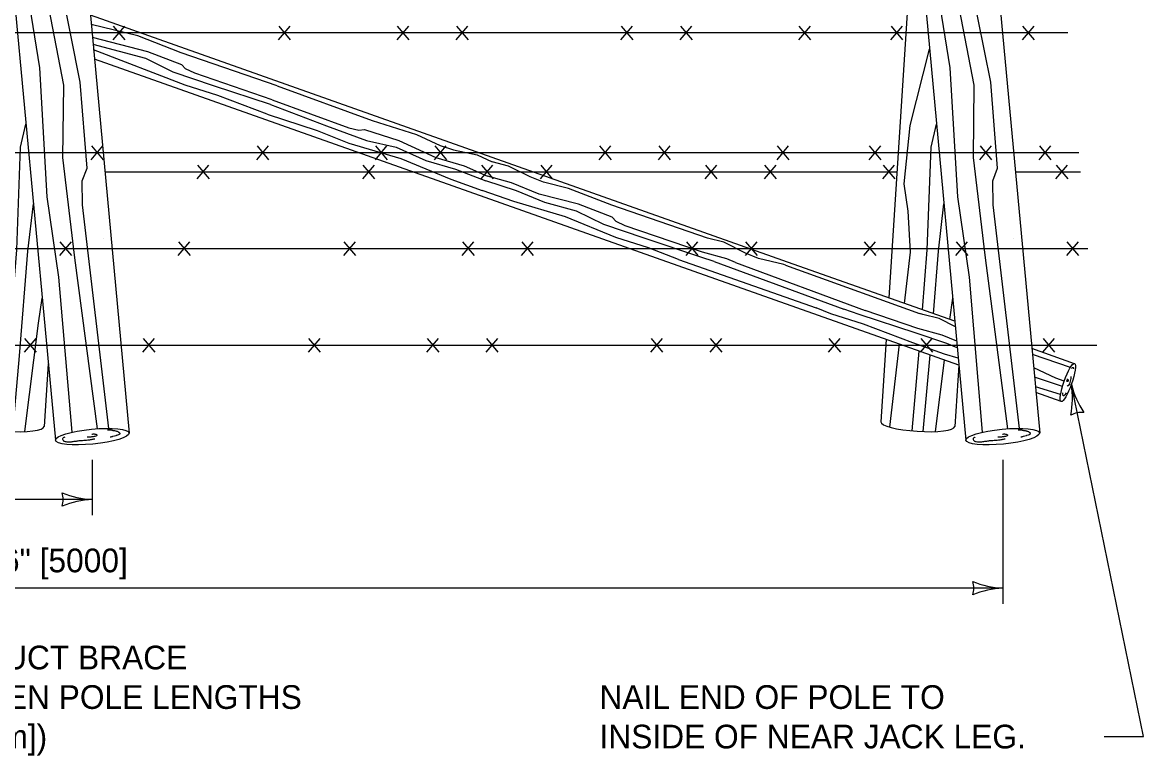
# Model space of a CAD drawing. Extents: x 49991.4 to 50021, y 49987.6 to 50011.4.
# Drawn here: x 50012.065 to 50014.903, y 49990.172 to 49992.027 of the extents above; entities that cross this region are included whole.
import ezdxf

# ---------------------------------------------------------------- set-up
doc = ezdxf.new("R2010")
doc.units = 0
for name, color, linetype in [('Level 1', 7, 'Continuous'), ('Level 2', 7, 'Continuous'), ('Level 3', 7, 'Continuous')]:
    doc.layers.add(name, color=color, linetype=linetype)

msp = doc.modelspace()

# ---------------------------------------------------------------- linework, layer by layer
at = {"layer": 'Level 1'}
for p, q in [((50014.3503, 49992.766), (50014.2579, 49991.3299)), ((50012.2063, 49992.3783), (50012.3358, 49990.9877)), ((50014.5108, 49992.3783), (50014.6403, 49990.9877)), ((50012.0223, 49992.3281), (50012.1488, 49990.9698)), ((50014.3268, 49992.3281), (50014.4534, 49990.9698)), ((50014.0306, 49991.4104), (50012.2373, 49992.0454)), ((50010.3579, 49992.001), (50012.6067, 49992.001)), ((50012.2948, 49991.9829), (50012.3242, 49992.0176)), ((50012.3255, 49991.9829), (50012.2962, 49992.0176)), ((50012.6067, 49992.001), (50014.7109, 49992.001)), ((50012.7136, 49991.9829), (50012.743, 49992.0176)), ((50012.7443, 49991.9829), (50012.715, 49992.0176)), ((50013.0136, 49991.9829), (50013.043, 49992.0176)), ((50013.0443, 49991.9829), (50013.015, 49992.0176)), ((50013.1636, 49991.9829), (50013.193, 49992.0176)), ((50013.1943, 49991.9829), (50013.165, 49992.0176)), ((50013.5803, 49991.9829), (50013.6096, 49992.0176)), ((50013.611, 49991.9829), (50013.5816, 49992.0176)), ((50013.7303, 49991.9829), (50013.7596, 49992.0176)), ((50013.761, 49991.9829), (50013.7316, 49992.0176)), ((50014.0303, 49991.9829), (50014.0596, 49992.0176)), ((50014.061, 49991.9829), (50014.0316, 49992.0176)), ((50014.2632, 49991.9829), (50014.2926, 49992.0176)), ((50014.2939, 49991.9829), (50014.2646, 49992.0176)), ((50014.5963, 49991.9829), (50014.6257, 49992.0176)), ((50014.627, 49991.9829), (50014.5977, 49992.0176)), ((50013.6705, 49991.4303), (50012.2476, 49991.9341)), ((50012.325, 49991.9265), (50012.325, 49991.9265)), ((50012.2398, 49991.6795), (50012.2692, 49991.7142)), ((50012.2705, 49991.6795), (50012.2412, 49991.7142)), ((50012.6586, 49991.6795), (50012.688, 49991.7142)), ((50012.6893, 49991.6795), (50012.66, 49991.7142)), ((50012.9586, 49991.6795), (50012.988, 49991.7142)), ((50012.9893, 49991.6795), (50012.96, 49991.7142)), ((50013.1086, 49991.6795), (50013.138, 49991.7142)), ((50013.1393, 49991.6795), (50013.11, 49991.7142)), ((50013.5253, 49991.6795), (50013.5546, 49991.7142)), ((50013.556, 49991.6795), (50013.5266, 49991.7142)), ((50013.6753, 49991.6795), (50013.7046, 49991.7142)), ((50013.706, 49991.6795), (50013.6766, 49991.7142)), ((50013.9753, 49991.6795), (50014.0046, 49991.7142)), ((50014.006, 49991.6795), (50013.9766, 49991.7142)), ((50014.2082, 49991.6795), (50014.2376, 49991.7142)), ((50014.2389, 49991.6795), (50014.2096, 49991.7142)), ((50014.4886, 49991.6795), (50014.518, 49991.7142)), ((50014.5193, 49991.6795), (50014.49, 49991.7142)), ((50014.6386, 49991.6795), (50014.668, 49991.7142)), ((50014.6693, 49991.6795), (50014.64, 49991.7142)), ((50010.3029, 49991.6976), (50012.5517, 49991.6976)), ((50012.5517, 49991.6976), (50014.7391, 49991.6976)), ((50012.5079, 49991.631), (50012.5373, 49991.6657)), ((50012.5386, 49991.631), (50012.5093, 49991.6657)), ((50012.9267, 49991.631), (50012.9561, 49991.6657)), ((50012.9574, 49991.631), (50012.9281, 49991.6657)), ((50013.2267, 49991.631), (50013.2561, 49991.6657)), ((50013.2574, 49991.631), (50013.2281, 49991.6657)), ((50013.3767, 49991.631), (50013.4061, 49991.6657)), ((50013.4074, 49991.631), (50013.3781, 49991.6657)), ((50013.7934, 49991.631), (50013.8227, 49991.6657)), ((50013.8241, 49991.631), (50013.7947, 49991.6657)), ((50013.9434, 49991.631), (50013.9727, 49991.6657)), ((50013.9741, 49991.631), (50013.9447, 49991.6657)), ((50014.2434, 49991.631), (50014.2727, 49991.6657)), ((50014.2741, 49991.631), (50014.2447, 49991.6657)), ((50014.6813, 49991.631), (50014.7107, 49991.6657)), ((50014.712, 49991.631), (50014.6827, 49991.6657)), ((50012.2742, 49991.6491), (50014.2792, 49991.6491)), ((50014.5776, 49991.6491), (50014.7436, 49991.6491)), ((50012.1598, 49991.4368), (50012.1892, 49991.4715)), ((50012.1905, 49991.4368), (50012.1612, 49991.4715)), ((50012.27, 49991.4793), (50012.27, 49991.4793)), ((50012.4598, 49991.4368), (50012.4892, 49991.4715)), ((50012.4905, 49991.4368), (50012.4612, 49991.4715)), ((50012.8786, 49991.4368), (50012.908, 49991.4715)), ((50012.9093, 49991.4368), (50012.88, 49991.4715)), ((50013.1786, 49991.4368), (50013.208, 49991.4715)), ((50013.2093, 49991.4368), (50013.18, 49991.4715)), ((50013.3286, 49991.4368), (50013.358, 49991.4715)), ((50013.3593, 49991.4368), (50013.33, 49991.4715)), ((50013.7453, 49991.4368), (50013.7746, 49991.4715)), ((50013.776, 49991.4368), (50013.7466, 49991.4715)), ((50013.8953, 49991.4368), (50013.9246, 49991.4715)), ((50013.926, 49991.4368), (50013.8966, 49991.4715)), ((50014.1953, 49991.4368), (50014.2246, 49991.4715)), ((50014.226, 49991.4368), (50014.1966, 49991.4715)), ((50014.4282, 49991.4368), (50014.4576, 49991.4715)), ((50014.4589, 49991.4368), (50014.4296, 49991.4715)), ((50014.5746, 49991.4793), (50014.5746, 49991.4793)), ((50014.7086, 49991.4368), (50014.738, 49991.4715)), ((50014.7393, 49991.4368), (50014.71, 49991.4715)), ((50010.5229, 49991.4549), (50012.7717, 49991.4549)), ((50012.7717, 49991.4549), (50014.7617, 49991.4549)), ((50014.4357, 49991.1592), (50013.6705, 49991.4302)), ((50013.7262, 49991.4272), (50014.0741, 49991.3049)), ((50013.8161, 49991.4222), (50014.1444, 49991.301)), ((50013.8701, 49991.4192), (50014.1984, 49991.2981)), ((50013.9969, 49991.4122), (50014.3362, 49991.2906)), ((50014.4254, 49991.2706), (50014.0306, 49991.4103)), ((50010.4335, 49991.2105), (50012.6823, 49991.2105)), ((50012.0704, 49991.1923), (50012.0998, 49991.227)), ((50012.1011, 49991.1923), (50012.0718, 49991.227)), ((50012.3704, 49991.1923), (50012.3998, 49991.227)), ((50012.4011, 49991.1923), (50012.3718, 49991.227)), ((50012.6823, 49991.2105), (50014.7845, 49991.2105)), ((50012.7892, 49991.1923), (50012.8186, 49991.227)), ((50012.8199, 49991.1923), (50012.7906, 49991.227)), ((50013.0892, 49991.1923), (50013.1186, 49991.227)), ((50013.1199, 49991.1923), (50013.0906, 49991.227)), ((50013.2392, 49991.1923), (50013.2686, 49991.227)), ((50013.2699, 49991.1923), (50013.2406, 49991.227)), ((50013.6559, 49991.1923), (50013.6852, 49991.227)), ((50013.6866, 49991.1923), (50013.6572, 49991.227)), ((50013.8059, 49991.1923), (50013.8352, 49991.227)), ((50013.8366, 49991.1923), (50013.8072, 49991.227)), ((50014.1059, 49991.1923), (50014.1352, 49991.227)), ((50014.1366, 49991.1923), (50014.1072, 49991.227)), ((50014.2511, 49991.2246), (50014.2377, 49991.0165)), ((50014.3388, 49991.1923), (50014.3682, 49991.227)), ((50014.3695, 49991.1923), (50014.3402, 49991.227)), ((50014.6479, 49991.1923), (50014.6773, 49991.227)), ((50014.6786, 49991.1923), (50014.6493, 49991.227)), ((50014.7283, 49991.1633), (50014.6204, 49991.2015)), ((50012.1308, 49991.1628), (50012.1208, 49991.0042)), ((50014.4352, 49991.1594), (50014.4253, 49991.0042)), ((50014.6944, 49991.0677), (50014.6307, 49991.0902))]:
    msp.add_line(p, q, dxfattribs=at)
for points in [[(50012.1909, 49990.9899), (50012.1576, 49991.3822), (50012.128, 49991.5856), (50012.1092, 49991.9121), (50012.0578, 49992.2317), (50012.0457, 49992.3433)], [(50012.255, 49990.9988), (50012.1983, 49991.4307), (50012.1677, 49991.6848), (50012.1698, 49991.8677), (50012.133, 49992.0604), (50012.1221, 49992.2455), (50012.1078, 49992.3553)], [(50012.2845, 49990.9996), (50012.2175, 49991.5649), (50012.217, 49991.6258), (50012.229, 49991.6576), (50012.2116, 49991.8755), (50012.1639, 49992.1145), (50012.1538, 49992.2929), (50012.1418, 49992.3594)], [(50014.4954, 49990.9899), (50014.4621, 49991.3822), (50014.4325, 49991.5856), (50014.4137, 49991.9121), (50014.3623, 49992.2317), (50014.3502, 49992.3433)], [(50014.5596, 49990.9988), (50014.5028, 49991.4307), (50014.4722, 49991.6848), (50014.4743, 49991.8677), (50014.4375, 49992.0604), (50014.4266, 49992.2455), (50014.4123, 49992.3553)], [(50014.589, 49990.9996), (50014.5221, 49991.5649), (50014.5216, 49991.6258), (50014.5335, 49991.6576), (50014.5161, 49991.8755), (50014.4685, 49992.1145), (50014.4583, 49992.2929), (50014.4464, 49992.3594)], [(50012.7099, 49991.8665), (50012.4673, 49991.9499), (50012.3576, 49991.9929), (50012.2395, 49992.0219)], [(50012.6973, 49991.8311), (50012.5016, 49991.8983), (50012.4784, 49991.9092), (50012.4686, 49991.9196), (50012.3827, 49991.9527), (50012.2425, 49991.9889)], [(50012.6931, 49991.8191), (50012.549, 49991.8666), (50012.4471, 49991.9013), (50012.378, 49991.9355), (50012.2442, 49991.971)], [(50012.6845, 49991.7948), (50012.56, 49991.8422), (50012.4774, 49991.8681), (50012.2455, 49991.9571)], [(50014.2976, 49991.3158), (50014.3128, 49991.4452), (50014.3073, 49991.5488), (50014.297, 49991.6186), (50014.312, 49991.7661), (50014.3612, 49991.9589)], [(50012.7099, 49991.8665), (50012.951, 49991.7787), (50013.0631, 49991.743), (50013.1224, 49991.7152), (50013.1562, 49991.7047), (50013.2162, 49991.6915), (50013.2547, 49991.6736)], [(50012.6973, 49991.8311), (50012.8918, 49991.7601), (50012.9165, 49991.754), (50012.9308, 49991.7558), (50013.0183, 49991.7276), (50013.1117, 49991.685), (50013.1838, 49991.6635), (50013.2421, 49991.6381)], [(50012.6931, 49991.8191), (50012.8348, 49991.7652), (50012.9361, 49991.7281), (50013.0111, 49991.7113), (50013.0865, 49991.6776), (50013.1612, 49991.6551), (50013.2379, 49991.6261)], [(50012.6845, 49991.7948), (50012.8111, 49991.7533), (50012.8916, 49991.7215), (50013.0235, 49991.6822), (50013.1494, 49991.6302), (50013.2293, 49991.6018)], [(50012.0124, 49990.9933), (50012.03, 49991.1858), (50012.0509, 49991.451), (50012.0608, 49991.711), (50012.0744, 49991.7691)], [(50014.3435, 49991.2996), (50014.3555, 49991.451), (50014.3653, 49991.711), (50014.3789, 49991.7691)], [(50013.7995, 49991.4807), (50013.557, 49991.5641), (50013.4474, 49991.6069), (50013.3838, 49991.6227), (50013.3508, 49991.6357), (50013.296, 49991.6633), (50013.2547, 49991.6736)], [(50013.787, 49991.4452), (50013.5912, 49991.5125), (50013.5681, 49991.5234), (50013.5582, 49991.5337), (50013.4724, 49991.5669), (50013.373, 49991.5924), (50013.3035, 49991.6212), (50013.2421, 49991.6381)], [(50013.7262, 49991.4272), (50013.6496, 49991.4564), (50013.5671, 49991.4823), (50013.4398, 49991.5347), (50013.3093, 49991.5736), (50013.2293, 49991.6018)], [(50013.7827, 49991.4332), (50013.6386, 49991.4807), (50013.5367, 49991.5154), (50013.4677, 49991.5496), (50013.3879, 49991.5708), (50013.3157, 49991.6004), (50013.2379, 49991.6261)], [(50012.041, 49990.9915), (50012.0584, 49991.1828), (50012.0794, 49991.4481), (50012.0931, 49991.5678)], [(50014.3714, 49991.2897), (50014.3839, 49991.4481), (50014.3977, 49991.5678)], [(50013.9969, 49991.4122), (50013.9921, 49991.4141), (50013.9287, 49991.4297), (50013.8956, 49991.4427), (50013.8407, 49991.4704), (50013.7995, 49991.4807)], [(50013.8161, 49991.4222), (50013.7827, 49991.4332)], [(50013.8701, 49991.4192), (50013.8484, 49991.4282), (50013.787, 49991.4452)], [(50012.0719, 49990.9916), (50012.1065, 49991.266), (50012.1153, 49991.3293)], [(50014.4123, 49991.2752), (50014.4199, 49991.3293)], [(50014.3189, 49991.2159), (50014.1944, 49991.2634), (50014.1118, 49991.2892), (50014.0741, 49991.3049)], [(50014.3275, 49991.2402), (50014.1835, 49991.2877), (50014.1444, 49991.301)], [(50014.3318, 49991.2522), (50014.1984, 49991.2981)], [(50014.3443, 49991.2877), (50014.3362, 49991.2906)], [(50014.4266, 49991.2567), (50014.3855, 49991.2774), (50014.3443, 49991.2877)], [(50014.4316, 49991.2038), (50014.4054, 49991.2146), (50014.3275, 49991.2402)], [(50014.4301, 49991.22), (50014.3932, 49991.2352), (50014.3318, 49991.2522)], [(50014.2609, 49991.0028), (50014.2855, 49991.2124)], [(50014.4341, 49991.1772), (50014.3988, 49991.1877), (50014.3189, 49991.2159)], [(50014.3169, 49990.9933), (50014.3354, 49991.1948)], [(50014.3455, 49990.9915), (50014.3632, 49991.1849)], [(50014.7178, 49991.1536), (50014.6217, 49991.1868)], [(50014.3764, 49990.9916), (50014.3992, 49991.1722)], [(50014.7021, 49991.1192), (50014.6809, 49991.1266), (50014.6249, 49991.153)], [(50014.6975, 49991.1053), (50014.6271, 49991.1293)], [(50014.6928, 49991.085), (50014.6294, 49991.105)], [(50014.7213, 49991.1138), (50014.7213, 49991.1138)]]:
    msp.add_lwpolyline(points, dxfattribs=at)
for centre, major_axis, ratio in [((50014.7113, 49991.1155), (0.0169, 0.0479), 0.196346), ((50012.2421, 49990.9788), (0.0932, 0.0089), 0.201992), ((50014.5466, 49990.9788), (0.0932, 0.0089), 0.201992)]:
    msp.add_ellipse(centre, major_axis=major_axis, ratio=ratio, dxfattribs=at)
for centre in [(50012.0269, 49991.0104), (50014.3314, 49991.0104)]:
    msp.add_ellipse(centre, major_axis=(-0.0937, 0.0061), ratio=0.194104, start_param=0.000064, end_param=3.132664, dxfattribs=at)
for points in [[(50014.721, 49991.151), (50014.722, 49991.153), (50014.7247, 49991.1535), (50014.7254, 49991.1529), (50014.726, 49991.1499)], [(50014.7124, 49991.1235), (50014.7101, 49991.118), (50014.7088, 49991.1191), (50014.7096, 49991.1212), (50014.7101, 49991.1251)], [(50014.7192, 49991.1306), (50014.7191, 49991.1258), (50014.7171, 49991.119), (50014.7122, 49991.1076), (50014.7092, 49991.1063)], [(50014.7069, 49991.0899), (50014.7042, 49991.0845), (50014.7017, 49991.0822), (50014.6995, 49991.0819), (50014.6993, 49991.0827), (50014.6983, 49991.0894)], [(50012.1725, 49990.9774), (50012.1702, 49990.9764), (50012.1676, 49990.9743), (50012.1669, 49990.9721), (50012.1681, 49990.97), (50012.1694, 49990.9679), (50012.1718, 49990.9669), (50012.1751, 49990.966), (50012.1809, 49990.9658), (50012.1892, 49990.9658), (50012.194, 49990.9666), (50012.1995, 49990.9671), (50012.2089, 49990.9686), (50012.2173, 49990.9692), (50012.2239, 49990.9697), (50012.2312, 49990.9703), (50012.2402, 49990.9718), (50012.2484, 49990.9731)], [(50012.2414, 49990.9851), (50012.2445, 49990.9855), (50012.2487, 49990.9851), (50012.2509, 49990.9848), (50012.2537, 49990.9833), (50012.2539, 49990.9816), (50012.2513, 49990.9798), (50012.2469, 49990.9787), (50012.2421, 49990.978), (50012.2386, 49990.9776), (50012.2331, 49990.9774), (50012.2303, 49990.9774), (50012.2294, 49990.9774)], [(50012.2808, 49990.9957), (50012.2854, 49990.9957), (50012.2899, 49990.9957), (50012.2931, 49990.995), (50012.2961, 49990.9942), (50012.3008, 49990.9936), (50012.3032, 49990.9927), (50012.3069, 49990.9915), (50012.3083, 49990.9907), (50012.3095, 49990.9895), (50012.311, 49990.9881), (50012.3119, 49990.9859), (50012.3113, 49990.9848), (50012.3087, 49990.9833), (50012.3032, 49990.9816), (50012.3014, 49990.981), (50012.2946, 49990.979), (50012.2922, 49990.9785), (50012.2891, 49990.9774), (50012.2877, 49990.9774)], [(50014.477, 49990.9774), (50014.4748, 49990.9764), (50014.4721, 49990.9743), (50014.4714, 49990.9721), (50014.4726, 49990.97), (50014.4739, 49990.9679), (50014.4763, 49990.9669), (50014.4796, 49990.966), (50014.4854, 49990.9658), (50014.4937, 49990.9658), (50014.4985, 49990.9666), (50014.504, 49990.9671), (50014.5134, 49990.9686), (50014.5218, 49990.9692), (50014.5284, 49990.9697), (50014.5358, 49990.9703), (50014.5448, 49990.9718), (50014.5529, 49990.9731)], [(50014.5459, 49990.9851), (50014.5491, 49990.9855), (50014.5533, 49990.9851), (50014.5554, 49990.9848), (50014.5582, 49990.9833), (50014.5584, 49990.9816), (50014.5558, 49990.9798), (50014.5514, 49990.9787), (50014.5466, 49990.978), (50014.5431, 49990.9776), (50014.5376, 49990.9774), (50014.5349, 49990.9774), (50014.5339, 49990.9774)], [(50014.5853, 49990.9957), (50014.59, 49990.9957), (50014.5944, 49990.9957), (50014.5977, 49990.995), (50014.6006, 49990.9942), (50014.6054, 49990.9936), (50014.6077, 49990.9927), (50014.6114, 49990.9915), (50014.6128, 49990.9907), (50014.6141, 49990.9895), (50014.6156, 49990.9881), (50014.6165, 49990.9859), (50014.6158, 49990.9848), (50014.6133, 49990.9833), (50014.6077, 49990.9816), (50014.6059, 49990.981), (50014.5991, 49990.979), (50014.5967, 49990.9785), (50014.5937, 49990.9774), (50014.5922, 49990.9774)]]:
    msp.add_spline(points, degree=3, dxfattribs=at)
at = {"layer": 'Level 3'}
for p, q in [((50012.2421, 49990.9198), (50012.2421, 49990.7798)), ((50014.5466, 49990.9198), (50014.5466, 49990.5554)), ((50012.2421, 49990.8198), (50009.9376, 49990.8198)), ((50014.5466, 49990.5954), (50009.9376, 49990.5954))]:
    msp.add_line(p, q, dxfattribs=at)
msp.add_lwpolyline([(50014.803, 49990.2198), (50014.903, 49990.2198), (50014.7202, 49991.1107)], dxfattribs=at)
for centre, radius, start, end in [((50014.5007, 49991.075), 0.2223, 349.0527, 9.2362), ((50014.9458, 49991.1687), 0.233, 194.424, 213.6738), ((50014.7459, 49990.9851), 0.0548, 83.7355, 119.4578), ((50012.2512, 49991.0419), 0.2223, 247.456, 267.6395), ((50012.1139, 49990.8198), 0.0548, 342.1388, 17.8612), ((50012.2536, 49990.587), 0.233, 92.8273, 112.0772), ((50014.5558, 49990.8176), 0.2223, 247.456, 267.6395), ((50014.4184, 49990.5954), 0.0548, 342.1388, 17.8612), ((50014.5581, 49990.3627), 0.233, 92.8273, 112.0772)]:
    msp.add_arc(centre, radius, start, end, dxfattribs=at)

# ---------------------------------------------------------------- texts
at = {"layer": 'Level 2'}
msp.add_text('16\'-6" [5000]', height=0.06, rotation=0, dxfattribs=at).set_placement((50011.8823, 49990.6354))
for s, p in [('CONSTRUCT BRACE', (50011.6802, 49990.3898)), ('EVERY TEN POLE LENGTHS ', (50011.6802, 49990.2898)), ('NAIL END OF POLE TO', (50013.526, 49990.2898)), ("(180' [55 m])", (50011.6802, 49990.1898)), ('INSIDE OF NEAR JACK LEG.', (50013.526, 49990.1898))]:
    msp.add_text(s, height=0.06, dxfattribs=at).set_placement(p)

doc.saveas('drawing.dxf')
